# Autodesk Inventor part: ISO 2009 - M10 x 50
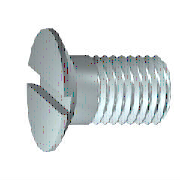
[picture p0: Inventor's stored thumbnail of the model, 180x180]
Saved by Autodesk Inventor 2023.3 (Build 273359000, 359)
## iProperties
Created: 2022-02
Part Number: ISO 2009 - M10 x 50
Material: Acier inoxydable 440C
Description: Vis à tête fraisée plate fendue (tête courante) - Produit de classe A
Document SubType Name: Modeling
Standard: ISO 2009
Designer: Thier
Standard Revision: Fourth edition 2011-09-01
Standards Organization: ISO
Language: fr-FR
Size Designation: M10 x 50 x 38
Categories: <MemberInstance><Categories><Category DisplayName="Visserie" InternalName="e4da775c-781d-43d5-af7c-5136215cf5a6" Mnemonic="FSTN"><Category DisplayName="Vis" Int
Density: 7.75 g/cm^3
Appearance: Semi-poli
IsCustomPart: 0
Author: Thier
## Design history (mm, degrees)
sketch "Esquisse1"
  geometry: L1 (5.92, 4.08)-(0.85, 9.15); L2 (0.85, 9.15)-(0, 9.15); L3 (0, 9.15)-(0, 0); L4 (0, 0)-(50, 0); L5 (50, 5)-(12, 5); L6 (12, 5)-(11.08, 4.08); L7 (11.08, 4.08)-(5.92, 4.08); L8 (12, 5)-(5, 5); L9 (50, 0)-(50, 5); L10 (-10, 0)-(60, 0) reference; L11 (0, 10.98)-(0, -1.83) reference
  constraints: 18 end point, 4 parallel, 2 collinear, 2 perpendicular, 1 horizontal, 1 point on line
  dimensions: "d0" = 50 distance of L3.end L4.end (= NLG); "d1" = 45 deg angle of L1 L4 (= 0.5 x SEWI); "d2" = 0.92018 horizontal distance of L5.end L6.end (= GAL); "d3" = 38 distance from line of L9 L5.end (= GEL); "d4" = 5 distance from line of L8.end L3 (= KOH); "d5" = 8.15965 diameter of L6.end L4 (= BDM); "d6" = 10 diameter of L5 L4 (= GD); "d7" = 18.3 diameter of L2 L4 (= KOD)
revolve "Corps" sketch "Esquisse1" stored, may be unused: angle "d19" = 90 deg
sketch "Esquisse2"
  geometry: L1 (9.15, -1.405)-(-9.15, -1.405); L2 (-9.15, -1.405)-(-9.15, 1.405); L3 (-9.15, 1.405)-(9.15, 1.405); L4 (9.15, 1.405)-(9.15, -1.405); L5 (0, 1.405)-(0, -1.405); L6 (-9.15, 0)-(9.15, 0); L7 (0, 9.15)-(0, 0) reference; 2 further points
  constraints: 12 end point, 5 midpoint, 2 parallel, 1 collinear, 1 horizontal, 1 perpendicular
  dimensions: "d15" = 2.81 distance of L3.end L1.start (= SBR); "d16" = 18.3 distance of L1.start L1.end (= KOD)
extrude "Rainure" cut sketch "Esquisse2" distance "d8" = 2.6 (= STI); taper "d9" = 0 deg
workplane "Work Plane1"
body "Solid1"
feature "Filetage" dims "d10" = 38 (= GEL), "d11" = 0
chamfer "Chanfrein1" distance "d12" = 0.92018 (= -0.5 x SPD + 0.5 x GD); stored, may be unused: second distance "d13" = 0.46009 (= 0.5 x GAL), angle "d35" = 45 deg
other parameters: "NLG" = 50 [user parameter; used in 1 equation term], "GAL" = 0.92018 (= 0.61345 x PTC) [user parameter; used in 2 equation terms], "GEL" = 38 [user parameter; used in 2 equation terms], "KOH" = 5 [user parameter; used in 1 equation term], "KOD" = 18.3 [user parameter; used in 2 equation terms], "SEWI" = 90 deg [user parameter; used in 1 equation term], "BDM" = 8.15965 (= NND - 1.2269 x PTC) [user parameter; used in 1 equation term], "GD" = 10 (= NND) [user parameter; used in 2 equation terms], "SBR" = 2.81 [user parameter; used in 1 equation term], "STI" = 2.6 [user parameter; used in 1 equation term], "d17" = 0, "SPD" = 8.15965 (= NND - 1.2269 x PTC) [user parameter; used in 1 equation term], "d39" = 0, "d40" = 0, "GUL" = 0.92018 (= 0.61345 x PTC) [user parameter], "PTC" = 1.5 [user parameter; used in 6 equation terms], "TOA" = 30 deg [user parameter], "TPU" = 6.66667 (computed from PTC) [user parameter], "GD1" = 8.15965 (= THREADDIA - 1.2269 x PTC) [user parameter]
